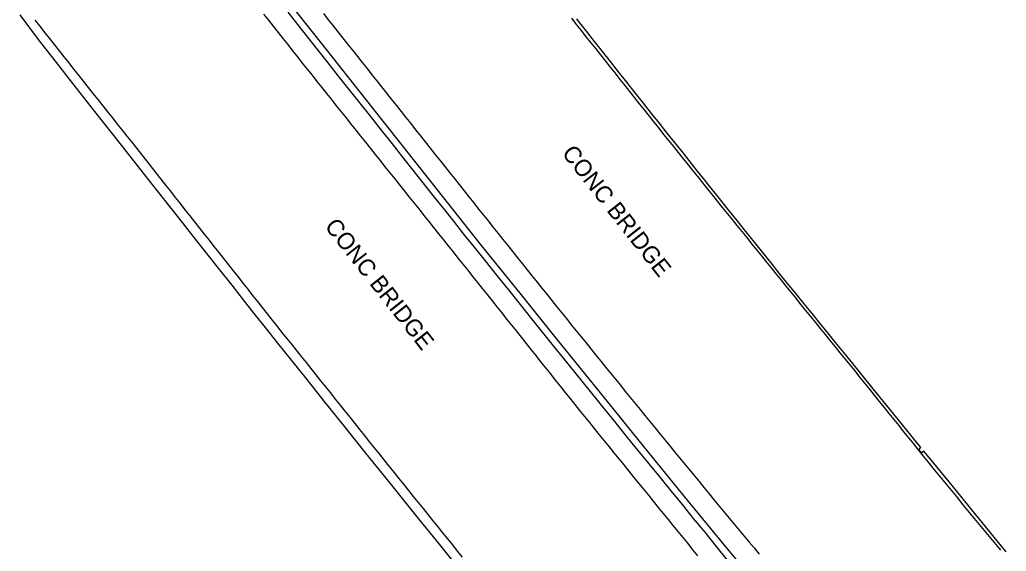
# Model space of a CAD drawing. Extents: x 1948091 to 1975253, y 787267 to 823306.
# Drawn here: x 1966330.8 to 1966647, y 801626.4 to 801796.8 of the extents above; entities that cross this region are included whole.
import ezdxf

# ---------------------------------------------------------------- set-up
doc = ezdxf.new("R2010")
doc.units = 0
for name, color, linetype in [('RD_EX_Bridge', 7, 'Continuous'), ('RD_EX_Pavement_Markings', 7, 'Continuous'), ('RD_TX_RoadID', 7, 'Continuous')]:
    doc.layers.add(name, color=color, linetype=linetype)

msp = doc.modelspace()

# ---------------------------------------------------------------- linework, layer by layer
at = {"layer": 'RD_EX_Bridge'}
for points in [[(1966415.31, 801804.61), (1966427.39, 801789.3), (1966437.86, 801775.99), (1966451.24, 801759.18), (1966463.04, 801744.33), (1966478.31, 801724.99), (1966491.49, 801708.6), (1966502.67, 801694.75), (1966518.23, 801675.47), (1966529.41, 801661.7), (1966543.23, 801644.64), (1966557.54, 801627.14), (1966568.31, 801614.35)], [(1966330.8, 801798.4), (1966336.67, 801790.43)], [(1966557.72, 801623.57), (1966554.14, 801627.98), (1966550.47, 801632.47), (1966546.83, 801636.94), (1966543.21, 801641.38), (1966539.61, 801645.8), (1966536.04, 801650.17), (1966532.53, 801654.48), (1966529.07, 801658.73), (1966525.66, 801662.92), (1966522.38, 801666.95), (1966516.43, 801674.29), (1966511.08, 801680.89), (1966505.17, 801688.24), (1966501.92, 801692.28), (1966498.52, 801696.53), (1966494.99, 801700.92), (1966491.33, 801705.48), (1966487.55, 801710.19), (1966483.77, 801714.9), (1966480.12, 801719.46), (1966476.6, 801723.86), (1966473.21, 801728.1), (1966469.9, 801732.25), (1966466.62, 801736.37), (1966463.38, 801740.46), (1966460.17, 801744.51), (1966456.94, 801748.59), (1966453.63, 801752.77), (1966450.25, 801757.03), (1966446.78, 801761.39), (1966443.3, 801765.77), (1966439.84, 801770.12), (1966436.41, 801774.43), (1966433.02, 801778.72), (1966429.66, 801782.95), (1966426.37, 801787.12), (1966423.13, 801791.24), (1966419.95, 801795.29), (1966416.81, 801799.28)], [(1966647.04, 801626.24), (1966645.56, 801628.01), (1966639.45, 801635.47), (1966636.05, 801639.65), (1966632.46, 801644.08), (1966628.69, 801648.7), (1966624.75, 801653.52), (1966620.63, 801658.54), (1966619.99, 801657.93), (1966619.02, 801658.93), (1966619.66, 801659.65), (1966613.78, 801666.92), (1966608.69, 801673.21), (1966604.38, 801678.52), (1966600.87, 801682.85), (1966597.84, 801686.57), (1966594.99, 801690.08), (1966592.32, 801693.36), (1966589.83, 801696.42), (1966587.39, 801699.42), (1966584.88, 801702.51), (1966582.29, 801705.7), (1966579.64, 801708.97), (1966576.95, 801712.29), (1966574.29, 801715.59), (1966571.63, 801718.89), (1966568.99, 801722.18), (1966566.33, 801725.5), (1966563.6, 801728.91), (1966560.8, 801732.41), (1966557.93, 801735.99), (1966555.11, 801739.51), (1966552.47, 801742.82), (1966549.99, 801745.92), (1966547.67, 801748.81), (1966545.42, 801751.63), (1966543.11, 801754.52), (1966540.76, 801757.47), (1966538.35, 801760.49), (1966535.89, 801763.59), (1966533.36, 801766.77), (1966530.76, 801770.04), (1966528.1, 801773.4), (1966525.42, 801776.77), (1966522.79, 801780.1), (1966520.19, 801783.38), (1966517.62, 801786.61), (1966515.07, 801789.83), (1966512.48, 801793.1), (1966509.87, 801796.39), (1966509.36, 801797.04)], [(1966336.67, 801790.43), (1966342.87, 801782.56), (1966348.92, 801774.88), (1966354.8, 801767.39), (1966360.53, 801760.1), (1966366.11, 801753.01), (1966371.54, 801746.13), (1966376.75, 801739.52), (1966381.68, 801733.27), (1966386.33, 801727.38), (1966390.71, 801721.85), (1966394.83, 801716.64), (1966398.74, 801711.71), (1966402.43, 801707.05), (1966405.89, 801702.67), (1966409.47, 801698.16), (1966413.48, 801693.11), (1966417.93, 801687.53), (1966422.81, 801681.42), (1966428.3, 801674.55), (1966434.58, 801666.71), (1966441.65, 801657.9), (1966449.51, 801648.11), (1966457.67, 801637.98), (1966465.63, 801628.12), (1966473.39, 801618.53)]]:
    msp.add_lwpolyline(points, dxfattribs=at)
at = {"layer": 'RD_EX_Pavement_Markings'}
for points in [[(1966408.98, 801798.61), (1966410.53, 801796.65), (1966412.08, 801794.69), (1966413.63, 801792.73), (1966415.18, 801790.77), (1966416.73, 801788.81), (1966418.28, 801786.85), (1966419.83, 801784.88), (1966421.38, 801782.92), (1966422.93, 801780.96), (1966424.49, 801779.01), (1966426.04, 801777.05), (1966427.6, 801775.1), (1966429.16, 801773.14), (1966430.72, 801771.19), (1966432.28, 801769.23), (1966433.84, 801767.28), (1966435.4, 801765.32), (1966436.95, 801763.37), (1966438.51, 801761.41), (1966440.07, 801759.46), (1966441.63, 801757.51), (1966443.19, 801755.55), (1966444.75, 801753.6), (1966446.31, 801751.65), (1966447.87, 801749.69), (1966449.43, 801747.74), (1966450.99, 801745.79), (1966452.55, 801743.83), (1966454.11, 801741.88), (1966455.67, 801739.93), (1966457.24, 801737.97), (1966458.8, 801736.02), (1966460.36, 801734.07), (1966461.92, 801732.11), (1966463.48, 801730.16), (1966465.04, 801728.21), (1966466.6, 801726.25), (1966468.16, 801724.3), (1966469.72, 801722.35), (1966471.28, 801720.39), (1966472.83, 801718.44), (1966474.39, 801716.48), (1966475.95, 801714.53), (1966477.51, 801712.57), (1966479.07, 801710.62), (1966480.63, 801708.67), (1966482.19, 801706.71), (1966483.75, 801704.76), (1966485.31, 801702.8), (1966486.87, 801700.85), (1966488.43, 801698.89), (1966489.99, 801696.94), (1966491.54, 801694.99), (1966493.1, 801693.03), (1966494.66, 801691.08), (1966496.22, 801689.12), (1966497.78, 801687.17), (1966499.34, 801685.21), (1966500.9, 801683.26), (1966502.46, 801681.3), (1966504.01, 801679.35), (1966505.57, 801677.39), (1966507.13, 801675.44), (1966508.69, 801673.49), (1966510.26, 801671.54), (1966511.83, 801669.59), (1966513.41, 801667.65), (1966514.98, 801665.71), (1966516.55, 801663.77), (1966518.13, 801661.83), (1966519.7, 801659.89), (1966521.28, 801657.94), (1966522.85, 801656), (1966524.43, 801654.06), (1966526, 801652.12), (1966527.58, 801650.18), (1966529.16, 801648.24), (1966530.73, 801646.3), (1966532.31, 801644.36), (1966533.89, 801642.42), (1966535.46, 801640.48), (1966537.04, 801638.54), (1966538.62, 801636.6), (1966540.19, 801634.66), (1966541.77, 801632.72), (1966543.35, 801630.78), (1966544.92, 801628.84), (1966546.5, 801626.9), (1966548.07, 801624.96)], [(1966428.15, 801798.75), (1966429.7, 801796.79), (1966431.26, 801794.83), (1966432.81, 801792.87), (1966434.36, 801790.92), (1966435.92, 801788.96), (1966437.47, 801787), (1966439.03, 801785.04), (1966440.58, 801783.08), (1966442.14, 801781.13), (1966443.69, 801779.17), (1966445.25, 801777.21), (1966446.8, 801775.25), (1966448.36, 801773.29), (1966449.91, 801771.34), (1966451.47, 801769.38), (1966453.02, 801767.42), (1966454.57, 801765.46), (1966456.13, 801763.51), (1966457.68, 801761.55), (1966459.24, 801759.59), (1966460.8, 801757.63), (1966462.35, 801755.68), (1966463.91, 801753.72), (1966465.46, 801751.76), (1966467.02, 801749.8), (1966468.57, 801747.85), (1966470.13, 801745.89), (1966471.68, 801743.93), (1966473.24, 801741.98), (1966474.79, 801740.02), (1966476.35, 801738.06), (1966477.9, 801736.1), (1966479.46, 801734.15), (1966481.02, 801732.19), (1966482.57, 801730.23), (1966484.13, 801728.28), (1966485.69, 801726.33), (1966487.26, 801724.38), (1966488.82, 801722.43), (1966490.39, 801720.48), (1966491.95, 801718.53), (1966493.51, 801716.58), (1966495.08, 801714.63), (1966496.64, 801712.68), (1966498.21, 801710.73), (1966499.77, 801708.78), (1966501.34, 801706.83), (1966502.9, 801704.88), (1966504.47, 801702.93), (1966506.03, 801700.98), (1966507.6, 801699.03), (1966509.18, 801697.09), (1966510.75, 801695.15), (1966512.32, 801693.2), (1966513.89, 801691.26), (1966515.47, 801689.32), (1966517.04, 801687.37), (1966518.61, 801685.43), (1966520.18, 801683.48), (1966521.75, 801681.54), (1966523.33, 801679.6), (1966524.9, 801677.65), (1966526.47, 801675.71), (1966528.05, 801673.77), (1966529.63, 801671.84), (1966531.22, 801669.9), (1966532.8, 801667.97), (1966534.39, 801666.04), (1966535.97, 801664.1), (1966537.56, 801662.17), (1966539.14, 801660.24), (1966540.73, 801658.3), (1966542.31, 801656.37), (1966543.9, 801654.44), (1966545.48, 801652.5), (1966547.07, 801650.57), (1966548.65, 801648.63), (1966550.24, 801646.7), (1966551.82, 801644.77), (1966553.4, 801642.83), (1966554.99, 801640.9), (1966556.59, 801638.98), (1966558.19, 801637.06), (1966559.78, 801635.13), (1966561.38, 801633.21), (1966562.98, 801631.29), (1966564.58, 801629.37), (1966566.18, 801627.45), (1966567.78, 801625.52)], [(1966507.67, 801797.26), (1966509.21, 801795.3), (1966510.76, 801793.33), (1966512.31, 801791.37), (1966513.87, 801789.42), (1966515.42, 801787.46), (1966516.98, 801785.5), (1966518.53, 801783.54), (1966520.09, 801781.58), (1966521.64, 801779.63), (1966523.19, 801777.67), (1966524.75, 801775.71), (1966526.3, 801773.75), (1966527.86, 801771.79), (1966529.41, 801769.83), (1966530.97, 801767.88), (1966532.52, 801765.92), (1966534.07, 801763.96), (1966535.63, 801762.01), (1966537.2, 801760.06), (1966538.76, 801758.11), (1966540.33, 801756.16), (1966541.89, 801754.21), (1966543.46, 801752.26), (1966545.02, 801750.31), (1966546.59, 801748.36), (1966548.15, 801746.41), (1966549.72, 801744.46), (1966551.28, 801742.51), (1966552.85, 801740.56), (1966554.41, 801738.61), (1966555.98, 801736.66), (1966557.55, 801734.71), (1966559.12, 801732.77), (1966560.69, 801730.83), (1966562.26, 801728.88), (1966563.83, 801726.94), (1966565.4, 801724.99), (1966566.97, 801723.05), (1966568.55, 801721.11), (1966570.12, 801719.16), (1966571.69, 801717.22), (1966573.26, 801715.27), (1966574.83, 801713.33), (1966576.41, 801711.38), (1966577.98, 801709.44), (1966579.55, 801707.5), (1966581.13, 801705.56), (1966582.7, 801703.62), (1966584.28, 801701.68), (1966585.85, 801699.73), (1966587.43, 801697.79), (1966589, 801695.85), (1966590.58, 801693.91), (1966592.15, 801691.97), (1966593.73, 801690.03), (1966595.3, 801688.08), (1966596.87, 801686.14), (1966598.45, 801684.2), (1966600.01, 801682.25), (1966601.58, 801680.3), (1966603.15, 801678.35), (1966604.72, 801676.41), (1966606.28, 801674.46), (1966607.85, 801672.51), (1966609.42, 801670.56), (1966610.98, 801668.62), (1966612.55, 801666.67), (1966614.12, 801664.72), (1966615.69, 801662.77), (1966617.25, 801660.82), (1966618.82, 801658.88), (1966620.39, 801656.93), (1966621.97, 801654.99), (1966623.55, 801653.06), (1966625.13, 801651.12), (1966626.71, 801649.18), (1966628.29, 801647.25), (1966629.88, 801645.31), (1966631.46, 801643.37), (1966633.04, 801641.44), (1966634.63, 801639.51), (1966636.22, 801637.58), (1966637.81, 801635.66), (1966639.41, 801633.73), (1966641, 801631.8), (1966642.59, 801629.88), (1966644.18, 801627.95), (1966645.2, 801626.73)], [(1966335.65, 801796.66), (1966337.2, 801794.7), (1966338.75, 801792.74), (1966340.3, 801790.78), (1966341.85, 801788.82), (1966343.41, 801786.86), (1966344.96, 801784.9), (1966346.51, 801782.94), (1966348.06, 801780.98), (1966349.61, 801779.02), (1966351.17, 801777.06), (1966352.73, 801775.1), (1966354.28, 801773.15), (1966355.84, 801771.19), (1966357.4, 801769.24), (1966358.95, 801767.28), (1966360.51, 801765.32), (1966362.07, 801763.37), (1966363.62, 801761.41), (1966365.18, 801759.46), (1966366.74, 801757.5), (1966368.29, 801755.54), (1966369.85, 801753.59), (1966371.4, 801751.62), (1966372.94, 801749.66), (1966374.48, 801747.69), (1966376.02, 801745.72), (1966377.57, 801743.75), (1966379.11, 801741.79), (1966380.65, 801739.82), (1966382.19, 801737.85), (1966383.74, 801735.89), (1966385.29, 801733.93), (1966386.84, 801731.97), (1966388.39, 801730.01), (1966389.95, 801728.05), (1966391.5, 801726.09), (1966393.05, 801724.13), (1966394.6, 801722.17), (1966396.16, 801720.21), (1966397.71, 801718.25), (1966399.26, 801716.29), (1966400.81, 801714.33), (1966402.36, 801712.37), (1966403.91, 801710.4), (1966405.46, 801708.44), (1966407.01, 801706.48), (1966408.56, 801704.52), (1966410.11, 801702.56), (1966411.66, 801700.6), (1966413.21, 801698.63), (1966414.76, 801696.67), (1966416.32, 801694.72), (1966417.88, 801692.77), (1966419.44, 801690.82), (1966421.01, 801688.87), (1966422.57, 801686.91), (1966424.13, 801684.96), (1966425.69, 801683.01), (1966427.26, 801681.06), (1966428.82, 801679.11), (1966430.38, 801677.15), (1966431.94, 801675.2), (1966433.5, 801673.25), (1966435.06, 801671.29), (1966436.62, 801669.34), (1966438.18, 801667.39), (1966439.74, 801665.43), (1966441.3, 801663.48), (1966442.86, 801661.53), (1966444.42, 801659.57), (1966445.98, 801657.62), (1966447.54, 801655.67), (1966449.1, 801653.71), (1966450.67, 801651.77), (1966452.24, 801649.82), (1966453.81, 801647.87), (1966455.37, 801645.93), (1966456.94, 801643.98), (1966458.51, 801642.03), (1966460.08, 801640.09), (1966461.65, 801638.14), (1966463.22, 801636.19), (1966464.79, 801634.25), (1966466.36, 801632.3), (1966467.92, 801630.35), (1966469.49, 801628.41), (1966471.06, 801626.46), (1966472.62, 801624.51)]]:
    msp.add_lwpolyline(points, dxfattribs=at)

# ---------------------------------------------------------------- texts
at = {"layer": 'RD_TX_RoadID'}
for p in [(1966504.35, 801753.95), (1966428.32, 801730.5)]:
    msp.add_text('CONC BRIDGE', height=5.4, rotation=308.1472, dxfattribs=at).set_placement(p)

doc.saveas('drawing.dxf')
